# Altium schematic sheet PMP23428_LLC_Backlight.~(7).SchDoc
size 431 x 279 mm; Date: Not shown in title block; ApprovedBy: Not shown in title block; CheckedBy: Not shown in title block; Author: Not shown in title block; CompanyName: Not shown in title block; Engineer: Not shown in title block; Organization: Not shown in title block; Address1: Not shown in title block; Address2: Not shown in title block; Address3: Not shown in title block; Address4: Not shown in title block; DocumentNumber: 2; Revision: Use project parameter SCH_Rev; SheetNumber: 2; SheetTotal: 4; PageSetup: Record=PageOptions¦CenterHorizontal=True¦CenterVertical=True¦PrintScale=1.00¦XCorrection=1.00¦YCorrection=1.00¦PrintKind=0¦BorderSize=5000000¦LeftOffset=0¦BottomOffset=0¦Orientation=2¦PaperLength=1000¦PaperWidth=1000¦Scale=100¦PaperSource=15¦PrintQuality=600¦MediaType=1¦DitherType=10¦PaperKind=Letter¦PrintScaleMode=1
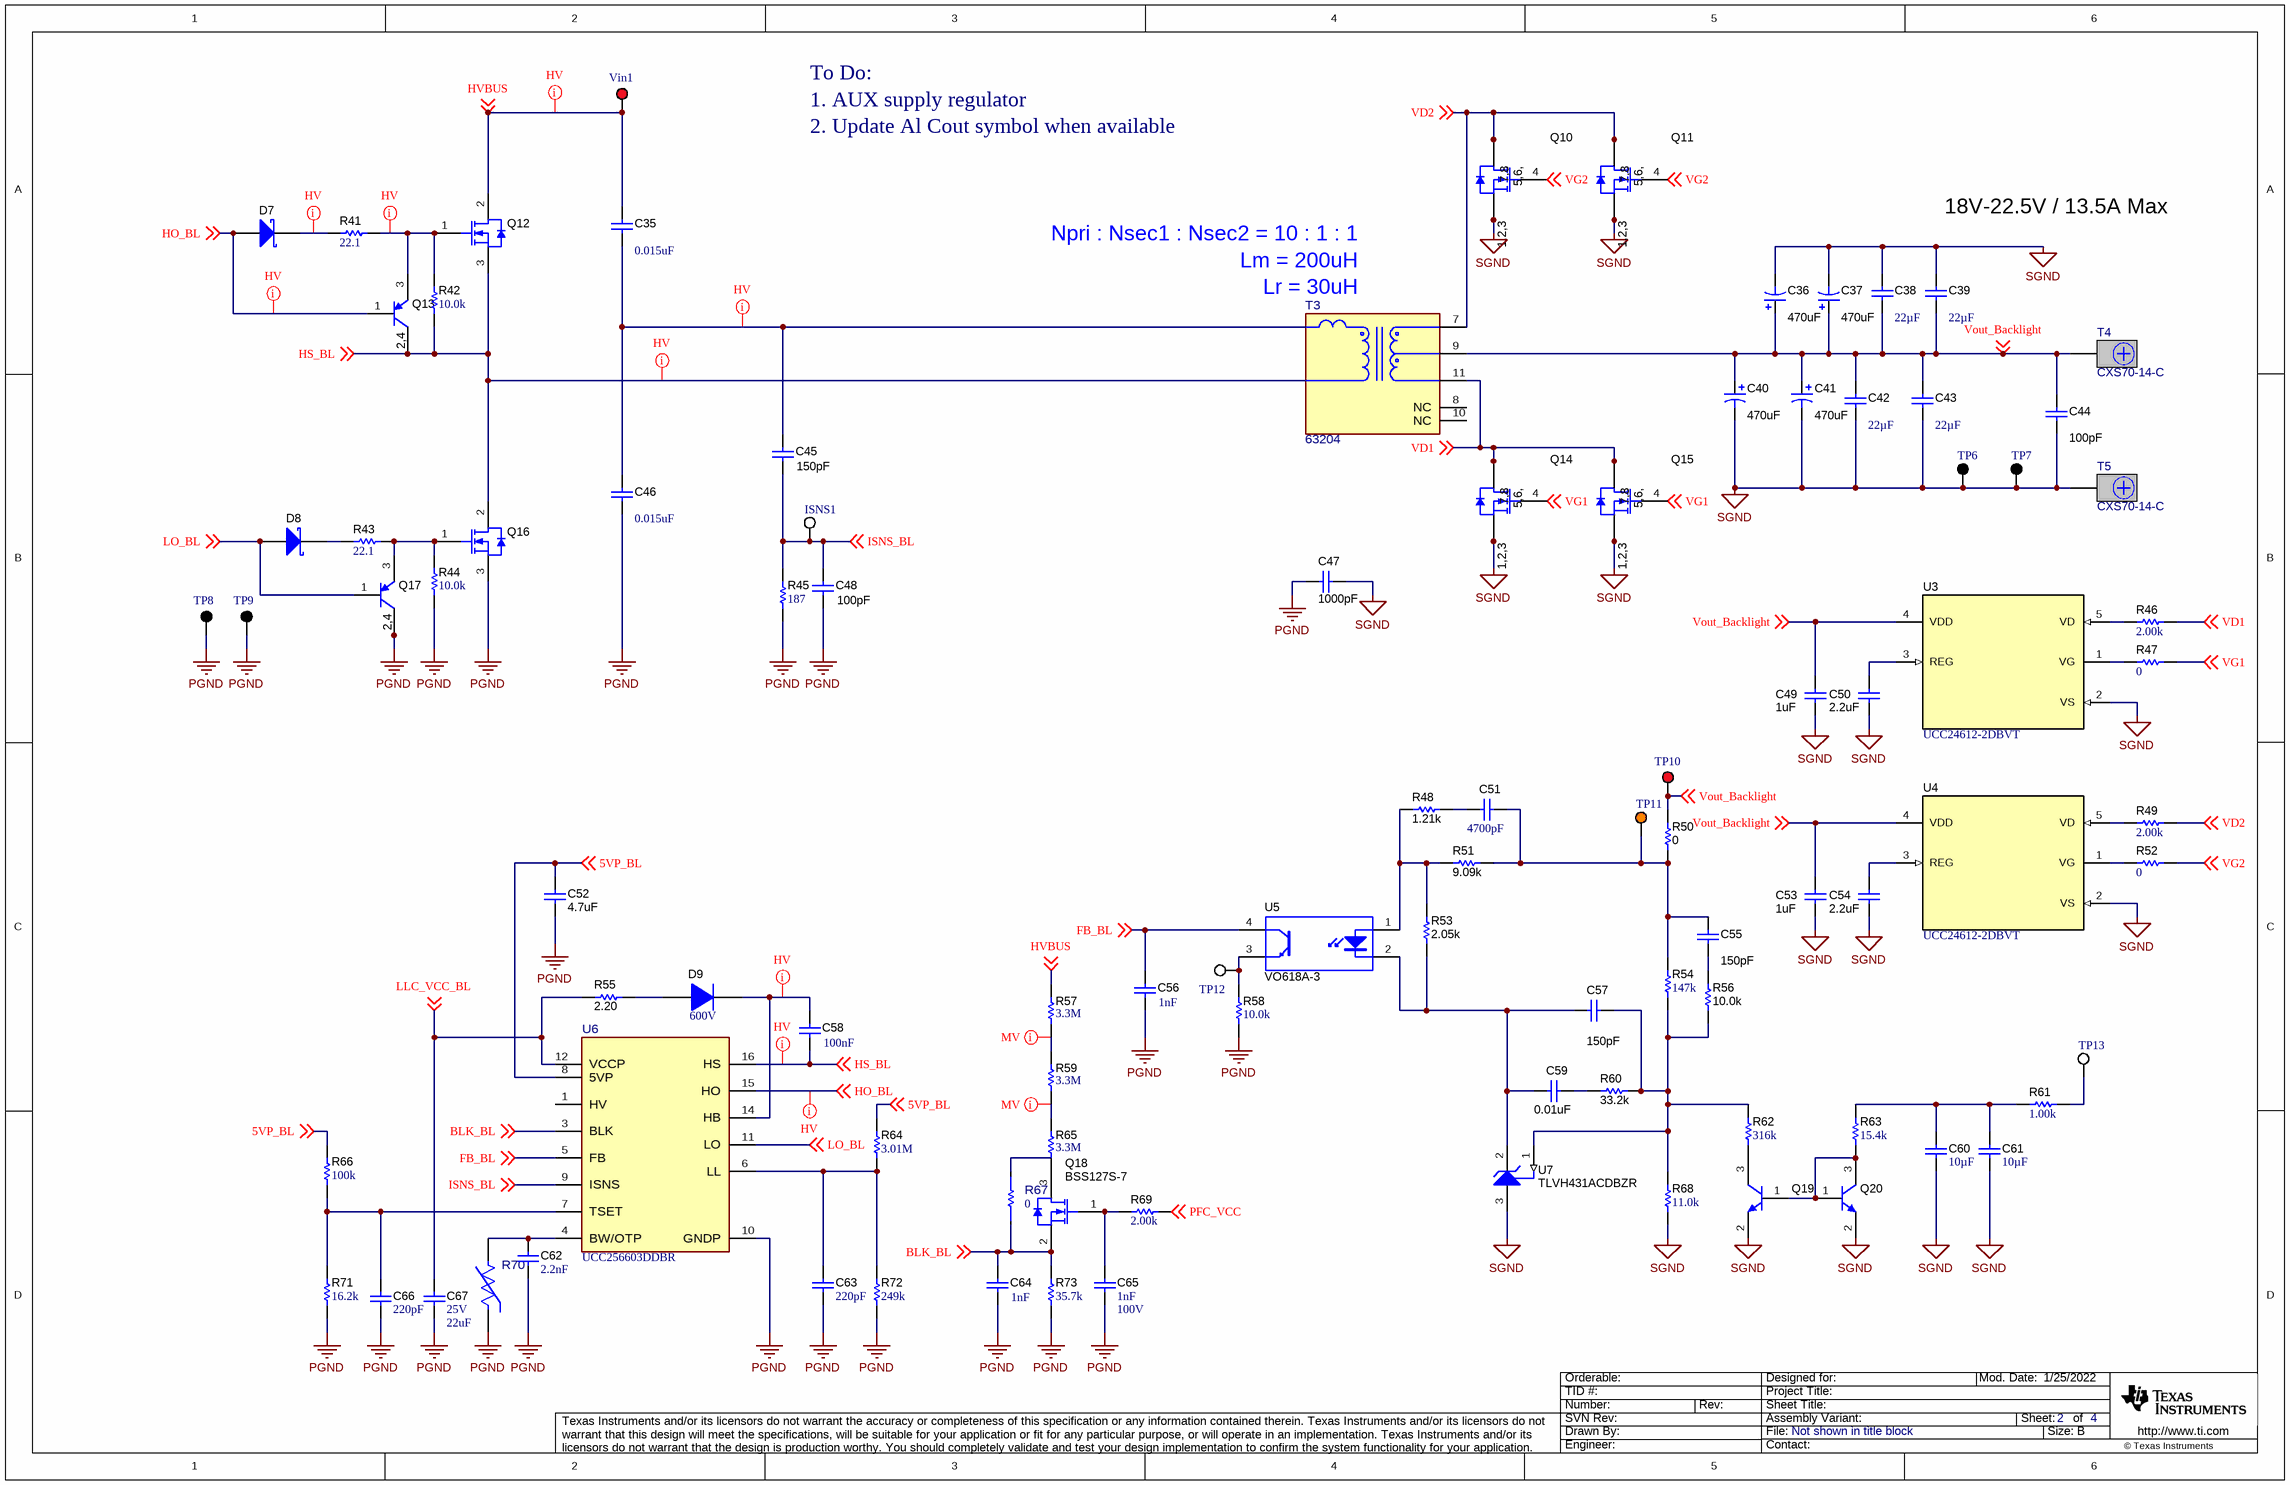
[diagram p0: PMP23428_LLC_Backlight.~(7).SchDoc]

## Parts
C35  ValueDisplayed: 0.015uF  [PHE426_1300x400x900]  (hidden comment: PHE426MA5150JR05)
C36  ValueDisplayed: 470uF  [HW_1000x1600]  (hidden comment: UHW1V471MPD)
C37  ValueDisplayed: 470uF  [HW_1000x1600]  (hidden comment: UHW1V471MPD)
C38  ValueDisplayed: 22µF  [1210]  (hidden comment: GMK325BJ226MM-P)
C39  ValueDisplayed: 22µF  [1210]  (hidden comment: GMK325BJ226MM-P)
C40  ValueDisplayed: 470uF  [HW_1000x1600]  (hidden comment: UHW1V471MPD)
C41  ValueDisplayed: 470uF  [HW_1000x1600]  (hidden comment: UHW1V471MPD)
C42  ValueDisplayed: 22µF  [1210]  (hidden comment: GMK325BJ226MM-P)
C43  ValueDisplayed: 22µF  [1210]  (hidden comment: GMK325BJ226MM-P)
C44  ValueDisplayed: 100pF  [0603L]  (hidden comment: 06035A101FAT2A)
C45  ValueDisplayed: 150pF  [1206L]  (hidden comment: GRM31A5C2J151JW01D)
C46  ValueDisplayed: 0.015uF  [PHE426_1300x400x900]  (hidden comment: PHE426MA5150JR05)
C47  ValueDisplayed: 1000pF  [CD45_700x600x1100]  (hidden comment: CD45-E2GA102M-NKA)
C48  ValueDisplayed: 100pF  [1206L]  (hidden comment: 12061A101JAT2A)
C49  ValueDisplayed: 1uF  [0603L]  (hidden comment: GRM188R71C105KE15D)
C50  ValueDisplayed: 2.2uF  [0805L]  (hidden comment: C2012X7R1V225K085AC)
C51  ValueDisplayed: 4700pF  [0603L]  (hidden comment: C0603C472J1GAC7867)
C52  ValueDisplayed: 4.7uF  [1206L]  (hidden comment: C3216X7R1E475K085AB)
C53  ValueDisplayed: 1uF  [0603L]  (hidden comment: GRM188R71C105KE15D)
C54  ValueDisplayed: 2.2uF  [0805L]  (hidden comment: C2012X7R1V225K085AC)
C55  ValueDisplayed: 150pF  [0402L]  (hidden comment: 885012005062)
C56  Cap_F: 1nF  [1206L]  (hidden comment: 12061A102JAT2A)
C57  ValueDisplayed: 150pF  [0402L]  (hidden comment: 885012005062)
C58  Cap_F: 100nF  [1206_180L]  (hidden comment: GRM31C5C1E104JA01L)
C59  ValueDisplayed: 0.01uF  [0603L]  (hidden comment: 06031C103JAT2A)
C60  ValueDisplayed: 10µF  [1206_180]  (hidden comment: C1206C106J3RACAUTO)
C61  ValueDisplayed: 10µF  [1206_180]  (hidden comment: C1206C106J3RACAUTO)
C62  Cap_F: 2.2nF  [0603]  (hidden comment: C0603X222K5RACTU)
C63  Cap_F: 220pF  [0603]  (hidden comment: C0603X221K5RACTU)
C64  Cap_F: 1nF  [0402L]  (hidden comment: 04025C102JAT2A)
C65  Cap_F: 1nF  VDC_V: 100V  [0603]  (hidden comment: C1608X7R2A102K080AA)
C66  Cap_F: 220pF  [0603]  (hidden comment: C0603X221K5RACTU)
C67  VDC_V: 25V  ValueDisplayed: 22uF  [1206_190]  (hidden comment: TMK316BBJ226ML-T)
D7  PMEG3010EGWJ  [SOD-123]  (value not drawn)
D8  PMEG3010EGWJ  [SOD-123]  (value not drawn)
D9  Vr_V: 600V  [SMAF]  (hidden comment: ES1JAF)
ISNS1  5012  [Keystone5012]  (value not drawn)
Q10  CSD19532Q5B  [DNK0008A]  (value not drawn)
Q11  CSD19532Q5B  [DNK0008A]  (value not drawn)
Q12  IPP60R099C7XKSA1  [TO-220AB]  (value not drawn)
Q13  FZT593TA  [SOT-223]  (value not drawn)
Q14  CSD19532Q5B  [DNK0008A]  (value not drawn)
Q15  CSD19532Q5B  [DNK0008A]  (value not drawn)
Q16  IPP60R099C7XKSA1  [TO-220AB]  (value not drawn)
Q17  FZT593TA  [SOT-223]  (value not drawn)
Q18  BSS127S-7  [SOT-23]
Q19  MMBTA05LT1G  [SOT-23]  (value not drawn)
Q20  MMBTA05LT1G  [SOT-23]  (value not drawn)
R41  ValueDisplayed: 22.1  [0603]  (hidden comment: RC0603FR-0722R1L)
R42  ValueDisplayed: 10.0k  [0603]  (hidden comment: M55342K12B10E0T)
R43  ValueDisplayed: 22.1  [0603]  (hidden comment: RC0603FR-0722R1L)
R44  ValueDisplayed: 10.0k  [0603]  (hidden comment: M55342K12B10E0T)
R45  ValueDisplayed: 187  [1206]  (hidden comment: RC1206FR-07187RL)
R46  ValueDisplayed: 2.00k  [0603]  (hidden comment: RC0603FR-072KL)
R47  ValueDisplayed: 0  [0603L]  (hidden comment: RC0603JR-070RL)
R48  ValueDisplayed: 1.21k  [0603L]  (hidden comment: RC0603FR-071K21L)
R49  ValueDisplayed: 2.00k  [0603]  (hidden comment: RC0603FR-072KL)
R50  ValueDisplayed: 0  [0402L]  (hidden comment: RC0402JR-070RL)
R51  ValueDisplayed: 9.09k  [0603L]  (hidden comment: RC0603FR-079K09L)
R52  ValueDisplayed: 0  [0603L]  (hidden comment: RC0603JR-070RL)
R53  ValueDisplayed: 2.05k  [0603L]  (hidden comment: RC0603FR-072K05L)
R54  ValueDisplayed: 147k  [0603L]  (hidden comment: RC0603FR-07147KL)
R55  ValueDisplayed: 2.20  [0603L]  (hidden comment: ERJ-3RQF2R2V)
R56  ValueDisplayed: 10.0k  [0603L]  (hidden comment: ERJ-3EKF1002V)
R57  Res_ohm: 3.3M  [FP-KTR18EZPF3304_1206-MFG]  (hidden comment: KTR18EZPF3304)
R58  ValueDisplayed: 10.0k  [0402L]  (hidden comment: ERJ-2RKF1002X)
R59  Res_ohm: 3.3M  [FP-KTR18EZPF3304_1206-MFG]  (hidden comment: KTR18EZPF3304)
R60  ValueDisplayed: 33.2k  [0603L]  (hidden comment: RC0603FR-0733K2L)
R61  ValueDisplayed: 1.00k  [0603L]  (hidden comment: CRCW06031K00FKEA)
R62  ValueDisplayed: 316k  [0603L]  (hidden comment: CRCW0603316KFKEA)
R63  ValueDisplayed: 15.4k  [0603L]  (hidden comment: RC0603FR-0715K4L)
R64  ValueDisplayed: 3.01M  [0603]  (hidden comment: RC0603FR-073M01L)
R65  Res_ohm: 3.3M  [FP-KTR18EZPF3304_1206-MFG]  (hidden comment: KTR18EZPF3304)
R66  ValueDisplayed: 100k  [0603]  (hidden comment: RC0603FR-07100KL)
R67  value 0  [FP-RMCF1206ZT0R00_1206-MFG]  (hidden comment: RMCF1206ZT0R00)
R68  ValueDisplayed: 11.0k  [0603]  (hidden comment: RC0603FR-0711KL)
R69  ValueDisplayed: 2.00k  [0603]  (hidden comment: RC0603FR-072KL)
R70  B57371V2474J060  [FP-B57371V2474J060_0603-MFG]  (value not drawn)
R71  ValueDisplayed: 16.2k  [0603]  (hidden comment: RC0603FR-0716K2L)
R72  ValueDisplayed: 249k  [0603]  (hidden comment: RC0603FR-07249KL)
R73  ValueDisplayed: 35.7k  [0603]  (hidden comment: RT0603BRD0735K7L)
T3  63204  [FP-63204_PTH_XRMS_80MM0_64MM0-MFG]
T4  CXS70-14-C  [Panduit_CXS70-14-C]
T5  CXS70-14-C  [Panduit_CXS70-14-C]
TP6  5011  [Keystone5011]  (value not drawn)
TP7  5011  [Keystone5011]  (value not drawn)
TP8  5011  [Keystone5011]  (value not drawn)
TP9  5011  [Keystone5011]  (value not drawn)
TP10  5010  [Keystone5010]  (value not drawn)
TP11  5013  [Keystone5013]  (value not drawn)
TP12  5012  [Keystone5012]  (value not drawn)
TP13  5012  [Keystone5012]  (value not drawn)
U3  UCC24612-2DBVT  [DBV0005A_N]
U4  UCC24612-2DBVT  [DBV0005A_N]
U5  VO618A-3  [DIP-4]
U6  UCC256603DDBR  [DDB0014A-MFG]
U7  TLVH431ACDBZR  [DBZ0003A_N]
Vin1  5010  [Keystone5010]  (value not drawn)

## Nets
PGND: C46.2 C47.2 C48.2 C52.2 C56.2 C62.2 C63.2 C64.2 C65.2 C66.2 C67.2 Q16.3(S) Q17.2(C) Q17.4(C) R44.1 R45.1 R58.1 R70.1 R71.1 R72.1 R73.1 TP8.1 TP9.1 U6.10(GNDP)
SGND: C36.2(-) C37.2(-) C38.1 C39.1 C40.2(-) C41.2(-) C42.2 C43.2 C44.2 C47.1 C49.2 C50.2 C53.2 C54.2 C60.2 C61.2 Q10.1(S) Q10.2(S) Q10.3(S) Q11.1(S) Q11.2(S) Q11.3(S) Q14.1(S) Q14.2(S) Q14.3(S) Q15.1(S) Q15.2(S) Q15.3(S) Q19.2(E) Q20.2(E) R68.1 T5.1 TP6.1 TP7.1 U3.2(VS) U4.2(VS) U7.3(ANODE)
5VP_BL: C52.1 R64.2 R66.2 U6.8(5VP) ; off-sheet 5VP_BL
BLK_BL: C64.1 Q18.2(S) R67.1 R73.2 U6.3(BLK) ; off-sheet BLK_BL
FB_BL: C56.1 U5.4(C) U6.5(FB) ; off-sheet FB_BL
HO_BL: D7.2(A) Q13.1(B) U6.15(HO) ; off-sheet HO_BL
HS_BL: C58.2 Q12.3(S) Q13.2(C) Q13.4(C) Q16.2(D) R42.1 U6.16(HS) ; off-sheet HS_BL
HVBUS: C35.1 Q12.2(D) R57.2 Vin1.1 ; off-sheet HVBUS
ISNS_BL: C45.2 C48.1 ISNS1.1 R45.2 U6.9(ISNS) ; off-sheet ISNS_BL
LLC_VCC_BL: C67.1 R55.1 U6.12(VCCP) ; off-sheet LLC_VCC_BL
LO_BL: D8.2(A) Q17.1(B) U6.11(LO) ; off-sheet LO_BL
PFC_VCC: R69.2 ; off-sheet PFC_VCC
VD1: Q14.5(D) Q14.6(D) Q14.7(D) Q14.8(D) Q14.9(D) Q15.5(D) Q15.6(D) Q15.7(D) Q15.8(D) Q15.9(D) R46.2 T3.11 ; off-sheet VD1
VD2: Q10.5(D) Q10.6(D) Q10.7(D) Q10.8(D) Q10.9(D) Q11.5(D) Q11.6(D) Q11.7(D) Q11.8(D) Q11.9(D) R49.2 T3.7 ; off-sheet VD2
VG1: Q14.4(G) Q15.4(G) R47.1 ; off-sheet VG1
VG2: Q10.4(G) Q11.4(G) R52.1 ; off-sheet VG2
Vout_Backlight: C36.1(+) C37.1(+) C38.2 C39.2 C40.1(+) C41.1(+) C42.1 C43.1 C44.1 C49.1 C53.1 R50.2 T3.9 T4.1 TP10.1 U3.4(VDD) U4.4(VDD) ; off-sheet Vout_Backlight
NetC35_2: C35.2 C45.1 C46.1
NetC50_1: C50.1 U3.3(REG)
NetC51_1: C51.1 C55.1 R50.1 R51.2 R54.2 TP11.1
NetC51_2: C51.2 R48.2
NetC54_1: C54.1 U4.3(REG)
NetC55_2: C55.2 R56.2
NetC57_1: C57.1 R54.1 R56.1 R60.1 R62.2 R68.2 U7.1(REF)
NetC57_2: C57.2 C59.2 R53.1 U5.2(K) U7.2(CATHODE)
NetC58_1: C58.1 D9.1(K) U6.14(HB)
NetC59_1: C59.1 R60.2
NetC60_1: C60.1 C61.1 R61.1 R63.2
NetC62_1: C62.1 R70.2 U6.4(BW/OTP)
NetC63_1: C63.1 R64.1 R72.2 U6.6(LL)
NetC65_1: C65.1 Q18.1(G) R69.1
NetC66_1: C66.1 R66.1 R71.2 U6.7(TSET)
NetD7_1: D7.1(K) R41.1
NetD8_1: D8.1(K) R43.1
NetD9_2: D9.2(A) R55.2
NetQ12_1: Q12.1(G) Q13.3(E) R41.2 R42.2
NetQ16_1: Q16.1(G) Q17.3(E) R43.2 R44.2
NetQ18_3: Q18.3(D) R65.1
NetQ19_1: Q19.1(B) Q20.1(B) Q20.3(C) R63.1
NetQ19_3: Q19.3(C) R62.1
NetR46_1: R46.1 U3.5(VD)
NetR47_2: R47.2 U3.1(VG)
NetR48_1: R48.1 R51.1 R53.2 U5.1(A)
NetR49_1: R49.1 U4.5(VD)
NetR52_2: R52.2 U4.1(VG)
NetR57_1: R57.1 R59.2
NetR58_2: R58.2 TP12.1 U5.3(E)
NetR59_1: R59.1 R65.2
NetR61_2: R61.2 TP13.1

Not connected (* = marked no-connect by the designer): R67 2; T3 8(NC) 10(NC); U6 1(HV)

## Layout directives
net class HV: HO_BL, HS_BL, HVBUS, NetC35_2, NetC58_1, NetD7_1, NetQ12_1
net class MV: NetR57_1, NetR59_1

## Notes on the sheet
- To Do:
- 1. AUX supply regulator
- 2. Update Al Cout symbol when available
- Npri : Nsec1 : Nsec2 = 10 : 1 : 1
- 18V-22.5V / 13.5A Max
- Lm = 200uH
- Lr = 30uH

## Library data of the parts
C35 C46 = CMP-0012541-3: CAP, Film, 0.015 uF, 630 V, +/- 20%, TH; Manufacturer: Kemet; TaMin_C: -55°C; Polarized: N; SizeAreaWB_mm2: 90; Value1: Unknown; TaMax_C: 105°C; SizeZ_mm: 9; SizeX_mm: 13; SizeY_mm: 4; Cap_Case: 13x4x9mm; Value2: 630V; SizeArea_mm2: 52; Cap_F: 15nF; AEC Category: Q200
C36 C37 C40 C41 = CMP-0010541-2: CAP, AL, 470 uF, 35 V, +/- 20%, 0.03 ohm, TH; Manufacturer: Nichicon; TaMin_C: -40°C; ESR_ohm: 0.03; Polarized: Y; SizeAreaWB_mm2: 144; U/M: EA; Value: 470uF; TaMax_C: 105°C; SizeZ_mm: 17.5; SizeX_mm: 10; Cap_Case: 10x16mm; Value2: 35V; SizeArea_mm2: 100; CompType: Capacitor; AEC Qualified: N; Cap_F: 470µF; IRMS_A: 2A; AEC Category: Q200
C38 C39 C42 C43 = CMP-0085817-1: CAP, CERM, 22 µF, 35 V,+/- 20%, X5R, 1210; Manufacturer: Taiyo Yuden; Value: 22uF; VDC_V: 35V; SizeZ_mm: 1.35; TaMax_C: 85°C; U/M: EA; SizeAreaWB_mm2: 14.7; SizeX_mm: 3.2; SizeArea_mm2: 8; TaMin_C: -55°C; AEC Qualified: N; SizeY_mm: 2.5; AEC Category: Q200
C44 = CMP-0006762-4: CAP, CERM, 100 pF, 50 V, +/- 1%, C0G/NP0, 0603; Manufacturer: AVX; TaMin_C: -55°C; Polarized: N; SizeAreaWB_mm2: 4.68; Value1: Unknown; U/M: EA; TaMax_C: 125°C; SizeZ_mm: 1; SizeX_mm: 1.6; SizeY_mm: 0.8; Cap_Case: 0603; Value2: 50V; SizeArea_mm2: 1.28; CompType: Capacitor; Value: 100pF; AEC Category: Q200
C45 = CMP-0008885-2: CAP, CERM, 150 pF, 630 V, +/- 5%, C0G/NP0, 1206; Manufacturer: MuRata; TaMin_C: -55°C; Polarized: N; SizeAreaWB_mm2: 10.92; Value1: Unknown; U/M: EA; Value: 150pF; TaMax_C: 125°C; SizeZ_mm: 1.35; SizeX_mm: 3.2; SizeY_mm: 1.6; Cap_Case: 1206; Value2: 630V; SizeArea_mm2: 5.12; CompType: Capacitor; AEC Category: Q200
C47 = CMP-0009595-2: CAP, CERM, 1000 pF,  V, +/- 20%, E, D7xT6mm; Manufacturer: TDK; TaMin_C: -25°C; Polarized: N; SizeAreaWB_mm2: 101.2; Value1: Unknown; U/M: EA; Value: 1000pF; TaMax_C: 125°C; SizeZ_mm: 11; SizeX_mm: 10.65; SizeY_mm: 6; Cap_Case: 7x6x11mm; SizeArea_mm2: 63.9; Cap_F: 1nF; AEC Category: Q200
C48 = CMP-0008462-2: CAP, CERM, 100 pF, 100 V, +/- 5%, C0G/NP0, 1206; Manufacturer: AVX; TaMin_C: -55°C; ESR_ohm: 7.01d; Polarized: N; SizeAreaWB_mm2: 10.92; Value1: 0.701 ohm; U/M: EA; Value: 100pF; TaMax_C: 125°C; SizeZ_mm: 1.35; SizeX_mm: 3.2; SizeY_mm: 1.6; Cap_Case: 1206; Value2: 100V; SizeArea_mm2: 5.12; CompType: Capacitor; AEC Category: Q200
C49 C53 = CMP-0007380-4: CAP, CERM, 1 uF, 16 V, +/- 10%, X7R, 0603; Manufacturer: MuRata; TaMin_C: -55°C; Polarized: N; SizeAreaWB_mm2: 4.68; Value1: Unknown; U/M: EA; Value: 1uF; TaMax_C: 125°C; SizeZ_mm: 1; SizeX_mm: 1.6; SizeY_mm: 0.8; Cap_Case: 0603; Value2: 16V; SizeArea_mm2: 1.28; CompType: Capacitor; Cap_F: 1µF; AEC Category: Q200
C50 C54 = CMP-0007883-2: CAP, CERM, 2.2 uF, 35 V, +/- 10%, X7R, 0805; Manufacturer: TDK; TaMin_C: -55°C; Polarized: N; SizeAreaWB_mm2: 6.75; Value1: Unknown; U/M: EA; Value: 2.2uF; TaMax_C: 125°C; SizeZ_mm: 1.45; SizeX_mm: 2; SizeY_mm: 1.25; Cap_Case: 0805; Value2: 35V; SizeArea_mm2: 2.5; CompType: Capacitor; Cap_F: 2.2µF; AEC Category: Q200
C51 = CMP-0006941-4: CAP, CERM, 4700 pF, 100 V, +/- 5%, C0G/NP0, 0603; Manufacturer: Kemet; TaMin_C: -55°C; Polarized: N; SizeAreaWB_mm2: 4.68; Value1: Unknown; U/M: EA; Value: 4700pF; TaMax_C: 125°C; SizeZ_mm: 1; SizeX_mm: 1.6; SizeY_mm: 0.8; Cap_Case: 0603; Value2: 100V; SizeArea_mm2: 1.28; Cap_F: 4.7nF; AEC Category: Q200
C52 = CMP-0008693-2: CAP, CERM, 4.7 uF, 25 V, +/- 10%, X7R, 1206; Manufacturer: TDK; TaMin_C: -55°C; Polarized: N; SizeAreaWB_mm2: 10.92; Value1: Unknown; U/M: EA; Value: 4.7uF; TaMax_C: 125°C; SizeZ_mm: 1.35; SizeX_mm: 3.2; SizeY_mm: 1.6; Cap_Case: 1206; Value2: 25V; SizeArea_mm2: 5.12; CompType: Capacitor; Cap_F: 4.7µF; AEC Category: Q200
C55 C57 = CMP-0064913-2: CAP, CERM, 150 pF, 50 V,+/- 5%, C0G/NP0, 0402; Manufacturer: Wurth Elektronik; TaMin_C: -55°C; Polarized: N; SizeAreaWB_mm2: 3; Value1: Unknown; U/M: EA; Value: 150pF; TaMax_C: 125°C; SizeZ_mm: 0.6; SizeX_mm: 1; SizeY_mm: 0.5; Cap_Case: 0402; Value2: 50V; CompType: Capacitor; AEC Category: Q200
C56 = CMP-0008465-2: CAP, CERM, 1000 pF, 100 V, +/- 5%, C0G/NP0, 1206; Manufacturer: AVX; TaMin_C: -55°C; ESR_ohm: 2.38d; Polarized: N; SizeAreaWB_mm2: 10.92; Value1: 0.238 ohm; U/M: EA; Value: 1000pF; TaMax_C: 125°C; SizeZ_mm: 1.35; SizeX_mm: 3.2; SizeY_mm: 1.6; Cap_Case: 1206; Value2: 100V; SizeArea_mm2: 5.12; AEC Category: Q200
C58 = CMP-0064950-2: CAP, CERM, 0.1 uF, 25 V,+/- 5%, C0G/NP0, 1206; Manufacturer: MuRata; TaMin_C: -55°C; Polarized: N; SizeAreaWB_mm2: 10.92; Value1: Unknown; U/M: EA; Value: 0.1uF; TaMax_C: 125°C; SizeZ_mm: 1.8; SizeX_mm: 3.2; SizeY_mm: 1.6; Cap_Case: 1206; Value2: 25V; SizeArea_mm2: 5.12; AEC Category: Q200
C59 = CMP-0006726-4: CAP, CERM, 0.01 uF, 100 V, +/- 5%, X7R, 0603; Manufacturer: AVX; TaMin_C: -55°C; ESR_ohm: 0.098; Polarized: N; SizeAreaWB_mm2: 4.68; Value1: 0.098 ohm; U/M: EA; Value: 0.01uF; TaMax_C: 125°C; SizeZ_mm: 1; SizeX_mm: 1.6; SizeY_mm: 0.8; Cap_Case: 0603; Value2: 100V; SizeArea_mm2: 1.28; Cap_F: 10nF; AEC Category: Q200
C60 C61 = CMP-0081062-1: CAP, CERM, 10 µF, 25 V,+/- 5%, X7R, AEC-Q200 Grade 1, 1206; Manufacturer: Kemet; TaMin_C: -55°C; Polarized: N; SizeAreaWB_mm2: 10.92; U/M: EA; Value: 10uF; TaMax_C: 125°C; SizeZ_mm: 1.8; SizeX_mm: 3.2; SizeY_mm: 1.6; Value2: 25V; SizeArea_mm2: 5.12; AEC Qualified: Y; AEC Grade: 1; AEC Category: Q200
C62 = CMP-0006983-4: CAP, CERM, 2200 pF, 50 V, +/- 10%, X7R, 0603; Manufacturer: Kemet; TaMin_C: -55°C; Polarized: N; SizeAreaWB_mm2: 4.68; Value1: Unknown; U/M: EA; Value: 2200pF; TaMax_C: 125°C; SizeZ_mm: 1; SizeX_mm: 1.6; SizeY_mm: 0.8; Value2: 50V; SizeArea_mm2: 1.28; AEC Category: Q200
C63 C66 = CMP-0006982-4: CAP, CERM, 220 pF, 50 V, +/- 10%, X7R, 0603; Manufacturer: Kemet; TaMin_C: -55°C; Polarized: N; SizeAreaWB_mm2: 4.68; Value1: Unknown; U/M: EA; Value: 220pF; TaMax_C: 125°C; SizeZ_mm: 1; SizeX_mm: 1.6; SizeY_mm: 0.8; Value2: 50V; SizeArea_mm2: 1.28; AEC Category: Q200
C64 = CMP-0861060-1: CAP, CERM, 1000 pF, 50 V,+/- 5%, X7R, 0402; Manufacturer: AVX; Value2: 50V; SizeY_mm: 0.5; AEC Category: Q200; Polarized: N; Green_Lifecycle: Active; SizeAreaWB_mm2: 3; ValueDisplayed: 1000pF; Cap_Case: 0402; Value: 1000pF; TaMin_C: -55°C; U/M: EA; Green_REACh: Passed; SizeZ_mm: 0.6; SizeX_mm: 1; TaMax_C: 125°C
C65 = CMP-0007053-4: CAP, CERM, 1000 pF, 100 V, +/- 10%, X7R, 0603; Manufacturer: TDK; TaMin_C: -55°C; Polarized: N; SizeAreaWB_mm2: 4.68; Value1: Unknown; U/M: EA; Value: 1000pF; TaMax_C: 125°C; SizeZ_mm: 1; SizeX_mm: 1.6; SizeY_mm: 0.8; SizeArea_mm2: 1.28; AEC Category: Q200
C67 = CMP-0009024-2: CAP, CERM, 22 uF, 25 V, +/- 20%, X5R, 1206_190; Manufacturer: Taiyo Yuden; TaMin_C: -55°C; Polarized: N; SizeAreaWB_mm2: 10.92; Value1: Unknown; U/M: EA; Value: 22uF; TaMax_C: 85°C; SizeZ_mm: 1.9; SizeX_mm: 3.2; SizeY_mm: 1.6; Cap_Case: 1206; SizeArea_mm2: 5.12; Cap_F: 22µF; AEC Category: Q200
D7 D8 = CMP-0079240-2: Diode, Schottky, 30 V, 1 A, AEC-Q101, SOD-123; Manufacturer: Nexperia; SizeZ_mm: 1.35; Value: 30V; Value1: 1A; AEC Category: Q101; Vf_V: 560mV; SizeX_mm: 3.85; SizeAreaWB_mm2: 13.095; Value2: 0.56V; SizeY_mm: 1.7; AEC Qualified: Y; TJmax_C: 150°C; SizeArea_mm2: 6.545
D9 = CMP-0029162-2: Diode, Ultrafast, 600 V, 1 A, AEC-Q101, SMAF; Manufacturer: Fairchild Semiconductor; Io_A: 1A; Green_Lifecycle: Not Set; SizeAreaWB_mm2: 19.95; Green_REACh: Incomplete; TJmax_C: 150°C; Value: 600V; SizeZ_mm: 1; SizeX_mm: 4.7; SizeY_mm: 2.5; Vf_V: 1.7V; SizeArea_mm2: 11.75; AEC Qualified: Y; AEC Category: Q101
ISNS1 TP12 = CMP-0055149-2: Test Point, Multipurpose, White, TH; Manufacturer: Keystone Electronics; CNHeader: FALSE; Green_Lifecycle: Active; Green_REACh: Passed; ContactFinish: Silver; CT: TRUE
Q10 Q11 Q14 Q15 = CMP-0000958-3: MOSFET, N-CH, 100 V, 17 A, DNK0008A (VSON-CLIP-8); Alternate Manufacturer: None; Manufacturer: Texas Instruments; SizeZ_mm: 1; ChType: N; Value2: 48 nC; VdsMax_V: 100V; SizeX_mm: 6; SizeY_mm: 5; Vgs_V: 20V; QgTyp_nC: 48; Value: 100V; SizeArea_mm2: 30; AEC Category: Q101; IdsMax_A: 17A; SizeAreaWB_mm2: 56; U/M: EA
Q12 Q16 = CMP-0001171-3: MOSFET, N-CH, 600 V, 22 A, TO-220AB; Alternate Manufacturer: None; Manufacturer: Infineon Technologies; SizeZ_mm: 19.4; ChType: N; Value2: 42 nC; VdsMax_V: 600V; SizeX_mm: 10.2; SizeY_mm: 4.5; Vgs_V: 30V; QgTyp_nC: 42; Value: 600V; SizeArea_mm2: 45.9; AEC Category: Q101; IdsMax_A: 22A; SizeAreaWB_mm2: 79.3; U/M: EA
Q13 Q17 = CMP-0000361-2: Transistor, PNP, 100 V, 1 A, AEC-Q101, SOT-223; Manufacturer: Diodes Inc.; TaMax_C: 150°C; Value2: 300; Value1: 1 A; Vcesat1_V: 3dV; SizeX_mm: 6.5; SizeY_mm: 7; TaMin_C: -55°C; IcRated_A: 1A; CompType: BJT; SizeZ_mm: 1.6; AEC Qualified: Y; Value: 100 V; SizeArea_mm2: 45.5; NPN: 0; Vceo_V: 100V; PNP: 1; AEC Category: Q101; SizeAreaWB_mm2: 76.5; U/M: EA
Q18 = CMP-0001149-3: MOSFET, N-CH, 600 V, 0.05 A, SOT-23; Alternate Manufacturer: None; Manufacturer: Diodes Inc.; SizeZ_mm: 1.1; ChType: N; Value2: 1.08 nC; VdsMax_V: 600V; SizeX_mm: 2.5; SizeY_mm: 3; Vgs_V: 20V; QgTyp_nC: 1.08; Value: 600V; SizeArea_mm2: 7.5; AEC Category: Q101; IdsMax_A: 50mA; SizeAreaWB_mm2: 14; U/M: EA
Q19 Q20 = CMP-0000488-2: Transistor, NPN, 60 V, 0.5 A, AEC-Q101, SOT-23; Manufacturer: ON Semiconductor; TaMax_C: 150°C; Value1: 0.5 A; Vcesat1_V: 2.5dV; SizeX_mm: 2.5; SizeY_mm: 3; TaMin_C: -55°C; IcRated_A: 5dA; CompType: BJT; SizeZ_mm: 1.1; AEC Qualified: Y; Value: 60 V; SizeArea_mm2: 7.5; NPN: 1; Vceo_V: 60V; PNP: 0; AEC Category: Q101; SizeAreaWB_mm2: 14; U/M: EA
R41 R43 = CMP-0022926-4: RES, 22.1, 1%, 0.1 W, 0603; Manufacturer: Yageo; Power_W: 100mW; TempCo: 100 ppm/C; Value_Code: 22R1; Value: 22.1; EIA_Code: E96; SizeX_mm: 1.6; SizeY_mm: 0.8; SizeZ_mm: 1; Value2: 0.1W; SizeArea_mm2: 1.28; AEC Qualified: N; VDC_V: 75V; AEC Category: Q200; SizeAreaWB_mm2: 4.68
R42 R44 = CMP-0080488-1: RES, 10.0 k, 1%, 0.1 W, 0603; Manufacturer: TT Electronics/IRC; Power_W: 100mW; TempCo: 100 ppm/C; SizeAreaWB_mm2: 4.68; Value_Code: 10k0; Value: 10.0k; EIA_Code: E96; Res_ohm: 10k; SizeX_mm: 1.6; SizeY_mm: 0.8; SizeZ_mm: 1; Value2: 0.1W; SizeArea_mm2: 1.28; AEC Qualified: N; AEC Category: Q200
R45 = CMP-0017949-2: RES, 187, 1%, 0.25 W, 1206; Manufacturer: Yageo America; Power_W: 250mW; TempCo: 100 ppm/C; Value_Code: 187R; U/M: EA; Value: 187; EIA_Code: E96; SizeX_mm: 3.2; SizeY_mm: 1.6; SizeZ_mm: 1.35; Value2: 0.25W; SizeArea_mm2: 5.12; VDC_V: 200V; AEC Category: Q200
R46 R49 R69 = CMP-0023000-5: RES, 2.00 k, 1%, 0.1 W, 0603; Manufacturer: Yageo; Power_W: 100mW; TempCo: 100 ppm/C; Value_Code: 2k00; Value: 2.00k; EIA_Code: E96; Res_ohm: 2k; SizeX_mm: 1.6; SizeY_mm: 0.8; SizeZ_mm: 1; Value2: 0.1W; SizeArea_mm2: 1.28; AEC Qualified: N; VDC_V: 75V; AEC Category: Q200; SizeAreaWB_mm2: 4.68
R47 R52 = CMP-0025885-5: RES, 0, 5%, 0.1 W, 0603; Manufacturer: Yageo; Power_W: 100mW; TempCo: 200 ppm/C; Value_Code: 0000; Value: 0; EIA_Code: E24; SizeX_mm: 1.6; SizeZ_mm: 1; Value2: 0.1W; SizeArea_mm2: 1.28; AEC Qualified: N; VDC_V: 75V; AEC Category: Q200; SizeY_mm: 0.8; SizeAreaWB_mm2: 4.68
R48 = CMP-0022871-5: RES, 1.21 k, 1%, 0.1 W, 0603; Manufacturer: Yageo; Power_W: 100mW; TempCo: 100 ppm/C; Value_Code: 1k21; Value: 1.21k; EIA_Code: E96; SizeX_mm: 1.6; SizeY_mm: 0.8; SizeZ_mm: 1; Value2: 0.1W; SizeArea_mm2: 1.28; AEC Qualified: N; VDC_V: 75V; AEC Category: Q200; SizeAreaWB_mm2: 4.68
R50 = CMP-0027004-2: RES, 0, 5%, 0.063 W, 0402; Manufacturer: Yageo America; Power_W: 63mW; TempCo: 200 ppm/C; Value_Code: 0000; U/M: EA; Value: 0; EIA_Code: E24; SizeX_mm: 1; SizeY_mm: 0.5; SizeZ_mm: 0.6; Value2: 0.063W; CompType: Resistor; VDC_V: 50V; AEC Category: Q200
R51 = CMP-0023332-5: RES, 9.09 k, 1%, 0.1 W, 0603; Manufacturer: Yageo; Power_W: 100mW; TempCo: 100 ppm/C; Value_Code: 9k09; Value: 9.09k; EIA_Code: E96; SizeX_mm: 1.6; SizeY_mm: 0.8; SizeZ_mm: 1; Value2: 0.1W; SizeArea_mm2: 1.28; AEC Qualified: N; VDC_V: 75V; AEC Category: Q200; SizeAreaWB_mm2: 4.68
R53 = CMP-0022981-5: RES, 2.05 k, 1%, 0.1 W, 0603; Manufacturer: Yageo; Power_W: 100mW; TempCo: 100 ppm/C; Value_Code: 2k05; Value: 2.05k; EIA_Code: E96; SizeX_mm: 1.6; SizeY_mm: 0.8; SizeZ_mm: 1; Value2: 0.1W; SizeArea_mm2: 1.28; AEC Qualified: N; VDC_V: 75V; AEC Category: Q200; SizeAreaWB_mm2: 4.68
R54 = CMP-0022800-4: RES, 147 k, 1%, 0.1 W, 0603; Manufacturer: Yageo; Power_W: 100mW; TempCo: 100 ppm/C; Value: 147k; EIA_Code: E96; SizeX_mm: 1.6; SizeY_mm: 0.8; SizeZ_mm: 1; Value2: 0.1W; SizeArea_mm2: 1.28; AEC Qualified: N; VDC_V: 75V; AEC Category: Q200; SizeAreaWB_mm2: 4.68
R55 = CMP-0022711-2: RES, 2.20, 1%, 0.1 W, 0603; Manufacturer: Panasonic; Power_W: 100mW; TempCo: 200 ppm/C; Value_Code: 2R20; U/M: EA; Value: 2.20; Res_ohm: 2.2; SizeX_mm: 1.6; SizeY_mm: 0.8; SizeZ_mm: 1; Value2: 0.1W; SizeArea_mm2: 1.28; CompType: Resistor; AEC Category: Q200
R56 = CMP-0022684-3: RES, 10.0 k, 1%, 0.1 W, 0603; Manufacturer: Panasonic; Power_W: 100mW; TempCo: 100 ppm/C; Value_Code: 10k0; U/M: EA; Value: 10.0k; EIA_Code: E96; Res_ohm: 10k; SizeX_mm: 1.6; SizeY_mm: 0.8; SizeZ_mm: 1; Value2: 0.1W; SizeArea_mm2: 1.28; CompType: Resistor; VDC_V: 75V; AEC Category: Q200
R57 R59 R65 = CMP-0087456-2: 3.3 MOhms ±1% 0.25W, 1/4W Chip Resistor 1206 (3216 Metric) Automotive AEC-Q200, High Voltage Thick Film; Manufacturer: Rohm Semiconductor; AEC Qualified: Yes; Power_W: 250mW; SizeZ_mm: 0.65mm; AEC Grade: Grade 0; TempCo: 100ppm/°C; VDC_V: 500V
R58 = CMP-0026658-1: RES, 10.0 k, 1%, 0.1 W, 0402; Manufacturer: Panasonic; Power_W: 100mW; TempCo: 100 ppm/C; Value_Code: 10k0; U/M: EA; Value: 10.0k; EIA_Code: E96; Res_ohm: 10k; SizeX_mm: 1; SizeY_mm: 0.5; SizeZ_mm: 0.6; Value2: 0.1W; VDC_V: 50V; AEC Category: Q200
R60 = CMP-0023036-5: RES, 33.2 k, 1%, 0.1 W, 0603; Manufacturer: Yageo; Power_W: 100mW; TempCo: 100 ppm/C; Value_Code: 33k2; Value: 33.2k; EIA_Code: E96; SizeX_mm: 1.6; SizeY_mm: 0.8; SizeZ_mm: 1; Value2: 0.1W; SizeArea_mm2: 1.28; AEC Qualified: N; VDC_V: 75V; AEC Category: Q200; SizeAreaWB_mm2: 4.68
R61 = CMP-0022109-5: RES, 1.00 k, 1%, 0.1 W, AEC-Q200 Grade 0, 0603; Manufacturer: Vishay-Dale; Power_W: 100mW; TempCo: 100 ppm/C; Value_Code: 1k00; Value: 1.00k; EIA_Code: E96; Res_ohm: 1k; SizeX_mm: 1.6; SizeY_mm: 0.8; SizeZ_mm: 1; Value2: 0.1W; SizeArea_mm2: 1.28; AEC Qualified: Y; VDC_V: 75V; AEC Category: Q200; AEC Grade: 0
R62 = CMP-0022328-4: RES, 316 k, 1%, 0.1 W, AEC-Q200 Grade 0, 0603; Manufacturer: Vishay-Dale; Power_W: 100mW; TempCo: 100 ppm/C; Value: 316k; EIA_Code: E96; SizeX_mm: 1.6; SizeY_mm: 0.8; SizeZ_mm: 1; Value2: 0.1W; SizeArea_mm2: 1.28; AEC Qualified: Y; VDC_V: 75V; AEC Category: Q200; AEC Grade: 0
R63 = CMP-0022814-5: RES, 15.4 k, 1%, 0.1 W, 0603; Manufacturer: Yageo; Power_W: 100mW; TempCo: 100 ppm/C; Value_Code: 15k4; Value: 15.4k; EIA_Code: E96; SizeX_mm: 1.6; SizeY_mm: 0.8; SizeZ_mm: 1; Value2: 0.1W; SizeArea_mm2: 1.28; AEC Qualified: N; VDC_V: 75V; AEC Category: Q200; SizeAreaWB_mm2: 4.68
R64 = CMP-0023092-4: RES, 3.01 M, 1%, 0.1 W, 0603; Manufacturer: Yageo; Power_W: 100mW; TempCo: 100 ppm/C; Value_Code: 3M01; Value: 3.01Meg; EIA_Code: E96; SizeX_mm: 1.6; SizeY_mm: 0.8; SizeZ_mm: 1; Value2: 0.1W; SizeArea_mm2: 1.28; AEC Qualified: N; VDC_V: 75V; AEC Category: Q200; SizeAreaWB_mm2: 4.68
R66 = CMP-0022735-5: RES, 100 k, 1%, 0.1 W, 0603; Manufacturer: Yageo; Power_W: 100mW; TempCo: 100 ppm/C; Value: 100k; EIA_Code: E96; SizeX_mm: 1.6; SizeY_mm: 0.8; SizeZ_mm: 1; Value2: 0.1W; SizeArea_mm2: 1.28; AEC Qualified: N; VDC_V: 75V; AEC Category: Q200; SizeAreaWB_mm2: 4.68
R67 = CMP-0093609-1: 0Ω ±0 0.25W 1206 Thick Film Chip Resistor AEC-Q200 compliant; Manufacturer: Stackpole Electronics; AEC Qualified: Yes; VDC_V: 200V; AEC Grade: Grade 0; Power_W: 250mW; SizeZ_mm: 0.7mm
R68 = CMP-0022763-5: RES, 11.0 k, 1%, 0.1 W, 0603; Manufacturer: Yageo; Power_W: 100mW; TempCo: 100 ppm/C; Value_Code: 11k0; Value: 11.0k; EIA_Code: E96; Res_ohm: 11k; SizeX_mm: 1.6; SizeY_mm: 0.8; SizeZ_mm: 1; Value2: 0.1W; SizeArea_mm2: 1.28; AEC Qualified: N; VDC_V: 75V; AEC Category: Q200; SizeAreaWB_mm2: 4.68
R70 = CMP-0096703-1: NTC Thermistor 470k 0603 (1608 Metric); Manufacturer: TDK; AEC Qualified: No; Res_ohm: 470kΩ; Power_W: 180mW; B 25 50: 4386K; B 25 100: 4480K; SizeZ_mm: 0.9mm; B 25 85: 4455K; B Tolerance: 3%; Tolerance_%: 5%
R71 = CMP-0022828-5: RES, 16.2 k, 1%, 0.1 W, 0603; Manufacturer: Yageo; Power_W: 100mW; TempCo: 100 ppm/C; Value_Code: 16k2; Value: 16.2k; EIA_Code: E96; SizeX_mm: 1.6; SizeY_mm: 0.8; SizeZ_mm: 1; Value2: 0.1W; SizeArea_mm2: 1.28; AEC Qualified: N; VDC_V: 75V; AEC Category: Q200; SizeAreaWB_mm2: 4.68
R72 = CMP-0022941-4: RES, 249 k, 1%, 0.1 W, 0603; Manufacturer: Yageo; Power_W: 100mW; TempCo: 100 ppm/C; Value: 249k; EIA_Code: E96; SizeX_mm: 1.6; SizeY_mm: 0.8; SizeZ_mm: 1; Value2: 0.1W; SizeArea_mm2: 1.28; AEC Qualified: N; VDC_V: 75V; AEC Category: Q200; SizeAreaWB_mm2: 4.68
R73 = CMP-0024147-3: RES, 35.7 k, 0.1%, 0.1 W, 0603; Manufacturer: Yageo America; Power_W: 100mW; TempCo: 25 ppm/C; Value_Code: 35k7; U/M: EA; Value: 35.7k; EIA_Code: E192; SizeX_mm: 1.6; SizeY_mm: 0.8; SizeZ_mm: 1; Value2: 0.1W; SizeArea_mm2: 1.28; VDC_V: 75V; AEC Category: Q200
T3 = CMP-0120310-1: Backlight LLC Transformer; Manufacturer: Payton Planar; Ind_H: 200µH; Ns1toNp: 10:1+1; SizeZ_mm: 10mm; AEC Qualified: No; Frequency_Fixed: 80-250kHz; TaMax_C: +30°C; TaMin_C: -40°C; Voltage_Isolation_Vrms: 2500VDC
T4 T5 = CMP-0075010-2: Terminal 70A Lug; Manufacturer: Panduit; CNHeader: False; Green_Lifecycle: Not Set; Green_REACh: Incomplete; CompType: Screw Terminal
TP6 TP7 = CMP-0055148-2: Test Point, Multipurpose, Black, TH; Manufacturer: Keystone Electronics; CNHeader: FALSE; ContactFinish: Silver; Green_REACh: Passed; Green_Lifecycle: Active; CT: TRUE
TP8 TP9 = CMP-0055148-2: Test Point, Multipurpose, Black, TH; Manufacturer: Keystone Electronics; CNHeader: FALSE; Green_Lifecycle: Active; Green_REACh: Passed; ContactFinish: Silver; CT: TRUE
TP10 Vin1 = CMP-0055147-2: Test Point, Multipurpose, Red, TH; Manufacturer: Keystone Electronics; CNHeader: FALSE; Green_Lifecycle: Active; Green_REACh: Passed; ContactFinish: Silver; CT: TRUE
TP11 = CMP-0055150-2: Test Point, Multipurpose, Orange, TH; Manufacturer: Keystone Electronics; CNHeader: FALSE; Green_Lifecycle: Active; Green_REACh: Passed; ContactFinish: Silver; CT: TRUE
TP13 = CMP-0055149-2: Test Point, Multipurpose, White, TH; Manufacturer: Keystone Electronics; ContactFinish: Silver; CT: TRUE; CNHeader: FALSE; Green_Lifecycle: Active; Green_REACh: Passed
U3 U4 = CMP-0013047-3: High-Frequency Multi-Mode Synchronous Rectifier Controller, DBV0005A (SOT-23-5); Manufacturer: Texas Instruments; Alternate PartNumber: UCC24612-2DBVR; SizeX_mm: 2.8; SizeY_mm: 2.9; CompType: IC; SizeZ_mm: 1.45; SizeArea_mm2: 8.12; SizeAreaWB_mm2: 14.82; AEC Category: Q200; AEC Qualified: N
U5 = CMP-0083653-1: Optocoupler, 5.3 kV, 100-200% CTR, SMT; Manufacturer: Vishay-Semiconductor; CTR (Max): 200%; SizeAreaWB_mm2: 71.064; CTR (Min): 100%; SizeZ_mm: 5; SizeX_mm: 8.8; SizeY_mm: 4.58; SizeArea_mm2: 40.304; Voltage_Isolation_Vrms: 5.3kV
U6 = CMP-0095299-1: 750kHz Wide VIN/VOUT Range LLC Controller Optimized for Light Load Efficiency; Manufacturer: Texas Instruments; Number Of Outputs: 2; TaMax_C: +125°C; Output Type: Other; TJmax_C: +150°C; AEC Qualified: No; Standoff Height: 0.1mm; TaMin_C: -40°C; SizeZ_mm: 1.75mm; Switching Frequency: 30-750kHz; Max Supply Voltage: 18.5V
U7 = CMP-0033066-1: Low-Voltage Adjustable Precision Shunt Regulator, 129 ppm / degC, 80 mA, 0 to 70 degC, 3-pin SOT-23 (DBZ), Green (RoHS & no Sb/Br); Manufacturer: Texas Instruments; Min Iz for Regulation(uA): 80; VO Adj(Max)(V): 18; VO Adj(Min)(V): 1.24; Rating: Catalog; SubFamily: Shunt Voltage Reference; Temp Coeff(Max)(ppm/ degree C): 129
